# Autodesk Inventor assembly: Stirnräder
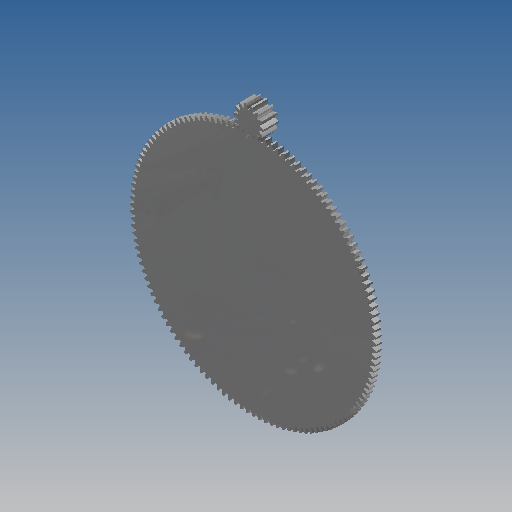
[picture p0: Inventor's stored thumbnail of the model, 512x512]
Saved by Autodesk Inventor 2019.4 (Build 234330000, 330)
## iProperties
Created: 2021-12
Part Number: Stirnräder
Document SubType Name: Assembly
Categories: <?xml version="1.0" encoding="UTF-16"?> <MemberInstance><Categories><FamilyTemplate/><ParamToTemplateMap><ParamToTemplate><ParamToTemplate CategoryParameter="//
Mass: 38.9908 g
Surface Area: 72.805 cm^2
Volume: 4.96698 cm^3
Density: 7.85 g/cm^3
ClientObjectVersion: 1
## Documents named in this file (3)
- C:\Zahn\Baugruppe1\Konstruktions-Assistent\Stirnräder1.iam
- C:\Zahn\Baugruppe1\Konstruktions-Assistent\Stirnzahnrad11.ipt
- C:\Zahn\Baugruppe1\Konstruktions-Assistent\Stirnzahnrad21.ipt
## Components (2 placed, 2 different names)
1. Stirnzahnrad1:1 — Drehung:1
2. Stirnzahnrad2:1 — Drehung:1
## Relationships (1: RelateRotation 1)
- Drehung:1 [RelateRotation]: Stirnzahnrad1:1 ↔ Stirnzahnrad2:1
